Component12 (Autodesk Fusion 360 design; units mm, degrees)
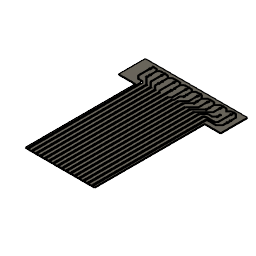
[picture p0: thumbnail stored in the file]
base_feature "Base Feature"
offset_faces "OffsetFaces1" distance -0.8
extrude "Extrude1" cut of existing geometry blind -0.6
